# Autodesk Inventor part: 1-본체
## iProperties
Created: 2014-11
Part Number: 1-본체
Document SubType Name: Modeling
Designer: elite
Density: 2.71 g/cm^3
Material: 알루미늄-6061
Mass: 2883.99 g
Surface Area: 2079.32 cm^2
Volume: 1064.2 cm^3
Author: elite
